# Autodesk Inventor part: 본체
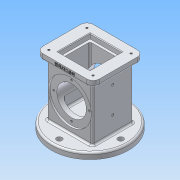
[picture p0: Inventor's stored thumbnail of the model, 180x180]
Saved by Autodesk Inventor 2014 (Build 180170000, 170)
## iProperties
Created: 2018-10
Part Number: 본체
Material: 알루미늄 6061
Document SubType Name: Modeling
Designer: Administrator
Density: 2.71 g/cm^3
Appearance: 알루미늄 - 평지
Mass: 989.657 g
Surface Area: 743.541 cm^2
Volume: 365.187 cm^3
Author: Administrator
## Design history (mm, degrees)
sketch "스케치1"
  geometry: C1 r 62.5 at (0, 0); 1 further point
  constraints: 1 centre point, 1 coincident
  dimensions: "d0" = 125 diameter of C1
extrude "돌출1" new body sketch "스케치1" distance "d1" = 10; taper "d2" = 0 deg
sketch "스케치2"
  geometry: L1 (-37, 33)-(37, 33); L2 (37, 33)-(37, -33); L3 (37, -33)-(-37, -33); L4 (-37, -33)-(-37, 33); L5 (-37, 33)-(37, -33); L6 (37, 33)-(-37, -33); C1 r 62.5 at (0, 0) reference
  constraints: 12 end point, 2 midpoint, 2 parallel, 1 horizontal, 1 perpendicular
  dimensions: "d3" = 74 distance of L2.end L3.end; "d4" = 66 distance of L1.end L2.end
extrude "돌출2" join sketch "스케치2" distance "d5" = 98; taper "d6" = 0 deg
sketch "스케치3"
  geometry: L1 (37, 33)-(-37, 33) reference; L2 (-37, 33)-(-37, -33) reference; L3 (-37, -33)-(37, -33) reference; L4 (37, -33)-(37, 33) reference; L5 (-46, 41)-(46, 41); L6 (46, 41)-(46, -41); L7 (46, -41)-(-46, -41); L8 (-46, -41)-(-46, 41); L9 (-46, 41)-(46, -41); L10 (46, 41)-(-46, -41); 1 further point
  constraints: 12 end point, 2 midpoint, 2 parallel, 1 horizontal, 1 perpendicular
  dimensions: "d7" = 92 distance of L6.end L7.end; "d8" = 82 distance of L5.end L6.end
extrude "돌출3" join sketch "스케치3" distance "d9" = 10; taper "d10" = 0 deg
sketch "스케치6"
  geometry: L1 (-25.5, -10)-(99.5, -10) reference; C1 r 35 at (37, 44); 2 further points
  constraints: 1 centre point, 1 midpoint, 1 vertical alignment
  dimensions: "d19" = 70 diameter of C1; "d20" = 54 distance from line of L1 C1.centre
extrude "돌출6" cut sketch "스케치6" distance "d21" = 3; taper "d22" = 0 deg
sketch "스케치7"
  geometry: C1 r 35 at (0, 0) reference; C2 r 24 at (0, 0); 1 further point
  constraints: 1 centre point, 1 coincident
  dimensions: "d23" = 48 diameter of C2
extrude "돌출7" cut sketch "스케치7" stored distance "d24" = 10; taper "d25" = 0 deg
sketch "스케치8"
  geometry: L1 (-26, 26)-(26, 26); L2 (26, 26)-(26, -26); L3 (26, -26)-(-26, -26); L4 (-26, -26)-(-26, 26); L5 (-26, 26)-(26, -26); L6 (26, 26)-(-26, -26); 1 further point
  constraints: 12 end point, 2 midpoint, 2 parallel, 1 horizontal, 1 perpendicular
  dimensions: "d26" = 52 distance of L2.end L3.end; "d27" = 52 distance of L1.end L2.end
extrude "돌출8" cut sketch "스케치8" distance "d28" = 8; taper "d29" = 0 deg
sketch "스케치9"
  geometry: L1 (-22, 22)-(22, 22); L2 (22, 22)-(22, -22); L3 (22, -22)-(-22, -22); L4 (-22, -22)-(-22, 22); L5 (-22, 22)-(22, -22); L6 (22, 22)-(-22, -22); 1 further point
  constraints: 12 end point, 2 midpoint, 2 parallel, 1 horizontal, 1 perpendicular
  dimensions: "d30" = 44 distance of L2.end L3.end; "d31" = 44 distance of L1.end L2.end
extrude "돌출9" cut sketch "스케치9" distance "d32" = 74; taper "d33" = 0 deg
sketch "스케치10"
  geometry: L1 (0, 0)-(-28, 0); L2 (-28, 0)-(-24.874, 17.727); L3 (-24.874, 17.727)-(0, 17.727); L4 (0, 17.727)-(0, 0)
  constraints: 8 end point, 1 horizontal, 1 parallel, 1 perpendicular
  dimensions: "d34" = 28 distance of L1.start L1.end; "d35" = 18 distance of L1.end L2.end; "d36" = 80 deg angle of L1 L2
revolve "회전1" sketch "스케치10" stored, may be unused: angle "d37" = 90 deg
fillet "모깎기1" dims "d38" = 3
fillet "모깎기2" dims "d39" = 3
fillet "모깎기3" dims "d40" = 3
fillet "모깎기4" dims "d41" = 10
fillet "모깎기5" dims "d42" = 3
chamfer "모따기1" distance "d43" = 1; stored, may be unused: second distance "d44" = 2, angle "d45" = 45 deg
fillet "모깎기6" dims "d46" = 3
fillet "모깎기7" dims "d47" = 3
fillet "모깎기8" dims "d48" = 3
fillet "모깎기9" dims "d49" = 3
sketch "스케치11"
  geometry: A1 r 10 centre (-36, 31) between (-36, 41) and (-46, 31) reference; A2 r 10 centre (-36, -31) between (-46, -31) and (-36, -41) reference; A3 r 10 centre (36, -31) between (36, -41) and (46, -31) reference; A4 r 10 centre (36, 31) between (46, 31) and (36, 41) reference; 5 further points
  constraints: 4 coincident
hole "구멍1" sketch "스케치11" at (-36, 31), (36, 31), (36, -31), (-36, -31) diameter "d50" = 3.242; stored, may be unused: countersink angle "d54" = 90 deg, drill point angle "d56" = 118 deg; dims "d51" = 4, "d52" = 4, "d53" = 2, "d55" = 6
sketch "스케치12"
  geometry: C1 r 24 at (0, 0) reference; 2 further points
  constraints: 1 vertical alignment
  dimensions: "d57" = 29 distance of C1.centre point (0, 29)
hole "구멍2" sketch "스케치12" at (0, 29) diameter "d58" = 3.242; stored, may be unused: countersink angle "d62" = 90 deg, drill point angle "d64" = 118 deg; dims "d59" = 4, "d60" = 4, "d61" = 2, "d63" = 6
node "작업축1"
sketch "스케치13"
  geometry: L1 (13, -32.5)-(13, 92.5) reference; 4 further points
  constraints: 2 horizontal alignment, 1 midpoint
  dimensions: "d68" = 37 distance from line of L1 point (-24, 30); "d69" = 43 distance of point (-67, 30) point (-24, 30)
hole "구멍3" sketch "스케치13" at (-24, 30), (-67, 30) diameter "d70" = 4.134; stored, may be unused: countersink angle "d74" = 90 deg, drill point angle "d76" = 118 deg; dims "d71" = 4, "d72" = 4, "d73" = 2, "d75" = 30
sketch "스케치14"
  geometry: L1 (72, 0)-(0, 0) reference; L2 (-10, 0)-(-10, -7) reference; 2 further points
  constraints: 1 other
  dimensions: "d77" = 4 distance from line of L1 point (36, -4); "d78" = 46 distance from line of L2 point (36, -4)
feature "엠보싱1" sketch "스케치14" dims "d79" = 0.5, "d80" = 0
sketch "스케치15"
  geometry: C1 r 59.5 at (0, 0) reference; C2 r 4.5 at (-50, 0); C3 r 4.5 at (50, 0)
  constraints: 2 centre point, 2 horizontal alignment
  dimensions: "d83" = 9 diameter of C2; "d84" = 9 diameter of C3; "d85" = 50 distance of C1.centre C2.centre; "d86" = 50 distance of C3.centre C1.centre
extrude "돌출10" cut sketch "스케치15" distance "d87" = 74; taper "d88" = 0 deg
sketch "스케치16"
  geometry: C1 r 59.5 at (0, 0) reference; C2 r 4.5 at (0, 50); C3 r 4.5 at (0, -50)
  constraints: 2 centre point, 2 vertical alignment
  dimensions: "d89" = 9 diameter of C2; "d90" = 9 diameter of C3; "d91" = 50 distance of C1.centre C2.centre; "d92" = 50 distance of C1.centre C3.centre
extrude "돌출11" cut sketch "스케치16" stored distance "d93" = 74; taper "d94" = 0 deg
node "솔리드1"
mirror "대칭1"
pattern_circular "원형 패턴1" dims angle "d66" = 360 deg
mirror "대칭2"
